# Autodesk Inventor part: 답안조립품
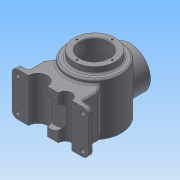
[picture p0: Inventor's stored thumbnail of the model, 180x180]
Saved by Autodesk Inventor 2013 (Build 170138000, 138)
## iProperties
Created: 2018-08
Part Number: 답안조립품
Material: 일반
Document SubType Name: Modeling
Designer: user
Density: 1 g/cm^3
Author: user
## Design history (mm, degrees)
sketch "스케치1"
  geometry: L1 (70, -40)-(-70, -40); L2 (-70, -40)-(-70, 40); L3 (-70, 40)-(70, 40); L4 (70, 40)-(70, -40); L5 (70, -40)-(-70, 40); L6 (-70, -40)-(70, 40); 1 further point
  constraints: 12 end point, 2 midpoint, 2 parallel, 1 horizontal, 1 perpendicular
  dimensions: "d0" = 140 distance of L2.end L3.end; "d1" = 80 distance of L1.end L2.end
extrude "돌출1" new body sketch "스케치1" distance "d2" = 10; taper "d3" = 0 deg
sketch "스케치4"
  geometry: L1 (82, 60)-(120, 60); L2 (120, 60)-(120, 48); L3 (120, 48)-(132, 48); L4 (132, 48)-(132, -48.671); L5 (82, 60)-(82, -60); L6 (0, 40)-(0, -40) reference; L7 (0, 40)-(10, 40) reference; A1 r 116 centre (82, 56) between (82, -60) and (132, -48.671); 1 further point
  constraints: 10 end point, 3 parallel, 2 point on circle, 1 centre point, 1 horizontal, 1 perpendicular, 1 point on line
  dimensions: "d6" = 116 radius of A1; "d7" = 108 distance from line of L5.end L3; "d9" = 76 diameter of L2 L5; "d10" = 82 distance from line of L6 L5.end; "d11" = 100 diameter of L4 L5; "d12" = 8 distance between parallel lines of L7 L3; "d13" = 12 distance of L1.end L2.end
revolve "회전1" sketch "스케치4" stored, may be unused: angle "d14" = 90 deg
sketch "스케치5"
  geometry: L1 (10, -40)-(0, -40) reference; L2 (0, -40)-(0, 40) reference; L3 (0, 40)-(10, 40) reference; L4 (10, 40)-(10, -40) reference; L5 (44, 48)-(44, 60) reference; L6 (44, 60)-(120, 60) reference; L7 (120, 60)-(120, 48) reference; L8 (120, 48)-(132, 48) reference; L9 (132, 48)-(132, -48.671) reference; L10 (32, -48.671)-(32, 48) reference; L11 (32, 48)-(44, 48) reference; L12 (122, 38)-(109, 38); L13 (109, 38)-(109, 60); L14 (39.614, 40.386)-(39.614, 40); L15 (82, 60)-(82, -50); L16 (122, 38)-(122, -42.163); L17 (109, 60)-(82, 60); A1 r 116 centre (82, 56) between (32, -48.671) and (82, -60) reference; A2 r 116 centre (82, 56) between (82, -60) and (132, -48.671) reference; A3 r 106 centre (82, 56) between (82, -50) and (122, -42.163); 1 further point
  constraints: 12 end point, 3 point on line, 2 parallel, 2 point on circle, 1 centre point, 1 collinear, 1 midpoint
  dimensions: "d18" = 10 radial gap between concentric circles of A1 A3; "d19" = 54 diameter of L13 L15; "d20" = 80 diameter of L16 L15; "d21" = 82 distance from line of L15.start L2; "d22" = 22 distance of L12.end L13.end
revolve "회전2" sketch "스케치5" stored, may be unused: angle "d23" = 90 deg
sketch "스케치6"
  geometry: L1 (-50, 40)-(50, 40); L2 (50, 40)-(50, -40); L3 (50, -40)-(-50, -40); L4 (-50, -40)-(-50, 40); L5 (-50, 40)-(50, -40); L6 (50, 40)-(-50, -40); 1 further point
  constraints: 12 end point, 2 midpoint, 2 parallel, 1 horizontal, 1 perpendicular
  dimensions: "d24" = 100 distance of L2.end L3.end; "d25" = 80 distance of L1.end L2.end
node "작업 평면2"
sketch "스케치7"
  geometry: C1 r 38 at (0, 0); 1 further point
  constraints: 1 centre point, 1 coincident
  dimensions: "d27" = 76 diameter of C1
extrude "돌출2" join sketch "스케치7" stored distance "d28" = 10; taper "d29" = 0 deg
sketch "스케치8" dims "d30" = 65
  geometry: 3 further points
  constraints: 1 coincident, 1 vertical alignment, 2 other
hole "구멍1" sketch "스케치8" at (0, 32.5) diameter "d31" = 3.242; stored, may be unused: countersink angle "d35" = 90 deg, drill point angle "d37" = 118 deg; dims "d32" = 8, "d33" = 4, "d34" = 2, "d36" = 10
sketch "스케치9"
  geometry: C1 r 25 at (0, 0); 1 further point
  constraints: 1 centre point, 1 coincident
  dimensions: "d41" = 50 diameter of C1
extrude "돌출3" cut sketch "스케치9" stored distance "d42" = 10; taper "d43" = 0 deg
sketch "스케치10" dims "d44" = 65
  geometry: C1 r 50 at (0, 0) reference; C2 r 38 at (0, 0) reference; 3 further points
  constraints: 1 coincident, 1 vertical alignment, 2 other
hole "구멍2" sketch "스케치10" at (0, 32.5) diameter "d45" = 3.242; stored, may be unused: countersink angle "d49" = 90 deg, drill point angle "d51" = 118 deg; dims "d46" = 8, "d47" = 4, "d48" = 2, "d50" = 10
node "작업 평면3"
node "작업 평면4"
sketch "스케치15" dims "d59" = 65
  geometry: C1 r 50 at (0, 82) reference; 3 further points
  constraints: 1 coincident, 1 vertical alignment, 2 other
  node "투영된 루프5"
extrude "돌출4" join sketch "스케치6" distance "d61" = 28.563; taper "d62" = 0 deg
sketch "스케치19"
  geometry: L1 (-70, 10)-(-50, 10) reference; L2 (-50, 38.563)-(-40.304, 52.41); L3 (-70, 0)-(-70, 10) reference; L4 (-24.763, 38.563)-(-50, 38.563); L5 (-50, 38.563)-(-24.763, 38.563); C1 r 38 at (0, 82) reference; A1 r 50 centre (0, 82) between (-40.304, 52.41) and (-24.763, 38.563); A2 r 50 centre (0, 82) between (-40.304, 52.41) and (-24.763, 38.563); 2 further points
  constraints: 6 end point, 4 point on circle, 2 centre point, 1 collinear, 3 other
  dimensions: "d63" = 35 deg angle of L3 L2
extrude "돌출5" join sketch "스케치19" stored distance "d64" = 80; taper "d65" = 0 deg
sketch "스케치20"
  geometry: L1 (-70, 40)-(70, 40) reference; L2 (70, 40)-(70, -40) reference; L3 (70, -40)-(-70, -40) reference; L4 (-70, -40)-(-70, 40) reference; L5 (70, 0)-(0, 0); C1 r 25 at (0, 0) reference; C2 r 4 at (60, 30); C3 r 4 at (60, -30); 1 further point
  constraints: 2 centre point, 2 end point, 1 midpoint, 1 perpendicular, 1 symmetric about line, 1 other
  dimensions: "d67" = 8 diameter of C2; "d68" = 10 distance from line of C2.centre L1; "d69" = 10 distance from line of C2.centre L2
extrude "돌출6" cut sketch "스케치20" stored distance "d70" = 8 (= d67); taper "d71" = 0 deg
sketch "스케치27"
  geometry: L1 (140, 0)-(0, 0) reference; A1 r 12.5 centre (42.5, 0) between (55, 0) and (30, 0); A2 r 17.5 centre (92.5, 0) between (110, 0) and (75, 0); 1 further point
  constraints: 4 point on circle, 4 point on line, 2 centre point
  dimensions: "d81" = 12.5 radius of A1; "d82" = 17.5 radius of A2; "d83" = 27.5 distance of point (70, 0) A1.centre; "d84" = 22.5 distance of A2.centre point (70, 0)
extrude "돌출7" cut sketch "스케치27" stored distance "d85" = 8 (= d67); taper "d86" = 0 deg
fillet "모깎기1" dims "d87" = 3
chamfer "모따기1" distance "d88" = 1; stored, may be unused: second distance "d89" = 2, angle "d90" = 45 deg
fillet "모깎기2" dims "d91" = 10
fillet "모깎기3" dims "d92" = 3
fillet "모깎기4" dims "d93" = 3
fillet "모깎기5" dims "d94" = 3
fillet "모깎기6" dims "d95" = 3
feature "엠보싱1" dims "d96" = 0.5, "d97" = 0
fillet "모깎기7" dims "d98" = 3
chamfer "모따기2" distance "d99" = 1; stored, may be unused: second distance "d100" = 2, angle "d101" = 45 deg
node "솔리드1"
pattern_circular "원형 패턴1" dims angle "d39" = 360 deg
pattern_circular "원형 패턴2" dims angle "d53" = 360 deg
mirror "대칭1"
mirror "대칭2"
node "투영된 루프2"
node "투영된 루프7"
node "투영된 루프8"
node "절단 모서리 투영1"
other parameters: "d26" = 147, "d57" = 0
